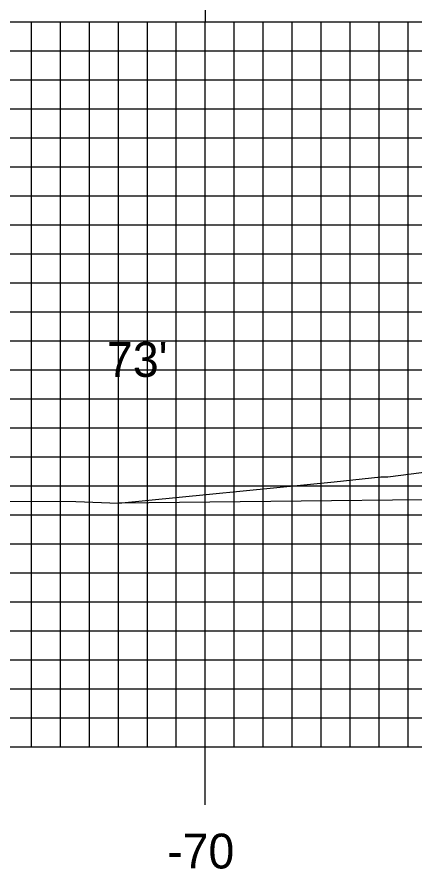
# Model space of a CAD drawing. Extents: x 852087 to 852430, y 366898 to 367118.
# Drawn here: x 852176.03 to 852189.77, y 366960.85 to 366990.23 of the extents above; entities that cross this region are included whole.
import ezdxf

# ---------------------------------------------------------------- set-up
doc = ezdxf.new("R2010")
doc.units = 0
for name, color, linetype in [('D_Roadway_Centerline', 7, 'Continuous'), ('D_Text_Standard', 7, 'Continuous'), ('H_V ANNOTATION', 7, 'Continuous'), ('MAJOR', 7, 'Continuous'), ('MINOR', 7, 'Continuous'), ('S_Roadway_Centerline', 7, 'Continuous')]:
    doc.layers.add(name, color=color, linetype=linetype)

msp = doc.modelspace()

# ---------------------------------------------------------------- linework, layer by layer
at = {"layer": 'D_Roadway_Centerline'}
msp.add_lwpolyline([(852198.346, 366973.65), (852196.346, 366973.65), (852179.534, 366973.462)], dxfattribs=at)
at = {"layer": 'MAJOR'}
for p, q in [((852182.531, 366992.071), (852182.531, 366990.067)), ((852112.531, 366990.067), (852392.531, 366990.067)), ((852112.531, 366990.067), (852392.531, 366990.067)), ((852182.531, 366965.067), (852182.531, 366990.067)), ((852112.531, 366985.067), (852392.531, 366985.067)), ((852112.531, 366980.067), (852392.531, 366980.067)), ((852112.531, 366975.067), (852392.531, 366975.067)), ((852112.531, 366970.067), (852392.531, 366970.067)), ((852112.531, 366965.067), (852392.531, 366965.067)), ((852112.531, 366965.067), (852392.531, 366965.067)), ((852182.531, 366963.063), (852182.531, 366965.067))]:
    msp.add_line(p, q, dxfattribs=at)
at = {"layer": 'MINOR'}
for p, q in [((852176.531, 366965.067), (852176.531, 366990.067)), ((852177.531, 366965.067), (852177.531, 366990.067)), ((852178.531, 366965.067), (852178.531, 366990.067)), ((852179.531, 366965.067), (852179.531, 366990.067)), ((852180.531, 366965.067), (852180.531, 366990.067)), ((852181.531, 366965.067), (852181.531, 366990.067)), ((852183.531, 366965.067), (852183.531, 366990.067)), ((852184.531, 366965.067), (852184.531, 366990.067)), ((852185.531, 366965.067), (852185.531, 366990.067)), ((852186.531, 366965.067), (852186.531, 366990.067)), ((852187.531, 366965.067), (852187.531, 366990.067)), ((852188.531, 366965.067), (852188.531, 366990.067)), ((852189.531, 366965.067), (852189.531, 366990.067)), ((852112.531, 366989.067), (852392.531, 366989.067)), ((852112.531, 366988.067), (852392.531, 366988.067)), ((852112.531, 366987.067), (852392.531, 366987.067)), ((852112.531, 366986.067), (852392.531, 366986.067)), ((852112.531, 366984.067), (852392.531, 366984.067)), ((852112.531, 366983.067), (852392.531, 366983.067)), ((852112.531, 366982.067), (852392.531, 366982.067)), ((852112.531, 366981.067), (852392.531, 366981.067)), ((852112.531, 366979.067), (852392.531, 366979.067)), ((852112.531, 366978.067), (852392.531, 366978.067)), ((852112.531, 366977.067), (852392.531, 366977.067)), ((852112.531, 366976.067), (852392.531, 366976.067)), ((852112.531, 366974.067), (852392.531, 366974.067)), ((852112.531, 366973.067), (852392.531, 366973.067)), ((852112.531, 366972.067), (852392.531, 366972.067)), ((852112.531, 366971.067), (852392.531, 366971.067)), ((852112.531, 366969.067), (852392.531, 366969.067)), ((852112.531, 366968.067), (852392.531, 366968.067)), ((852112.531, 366967.067), (852392.531, 366967.067)), ((852112.531, 366966.067), (852392.531, 366966.067))]:
    msp.add_line(p, q, dxfattribs=at)
at = {"layer": 'S_Roadway_Centerline'}
msp.add_lwpolyline([(852112.531, 366973.863), (852124.679, 366973.487), (852133.774, 366973.357), (852140.47, 366973.346), (852149.481, 366973.274), (852162.384, 366973.27), (852171.723, 366973.531), (852178.063, 366973.523), (852179.534, 366973.462), (852186.982, 366974.202), (852188.594, 366974.376), (852188.839, 366974.381), (852191.071, 366974.666), (852199.747, 366975.695), (852204.722, 366976.201), (852217.909, 366978.1)], dxfattribs=at)

# ---------------------------------------------------------------- texts
at = {"layer": 'D_Text_Standard'}
msp.add_text("73'", height=1.2, dxfattribs=at).set_placement((852179.137, 366977.824))
at = {"layer": 'H_V ANNOTATION'}
msp.add_text('-70', height=1.2, dxfattribs=at).set_placement((852181.214, 366960.867))

doc.saveas('drawing.dxf')
